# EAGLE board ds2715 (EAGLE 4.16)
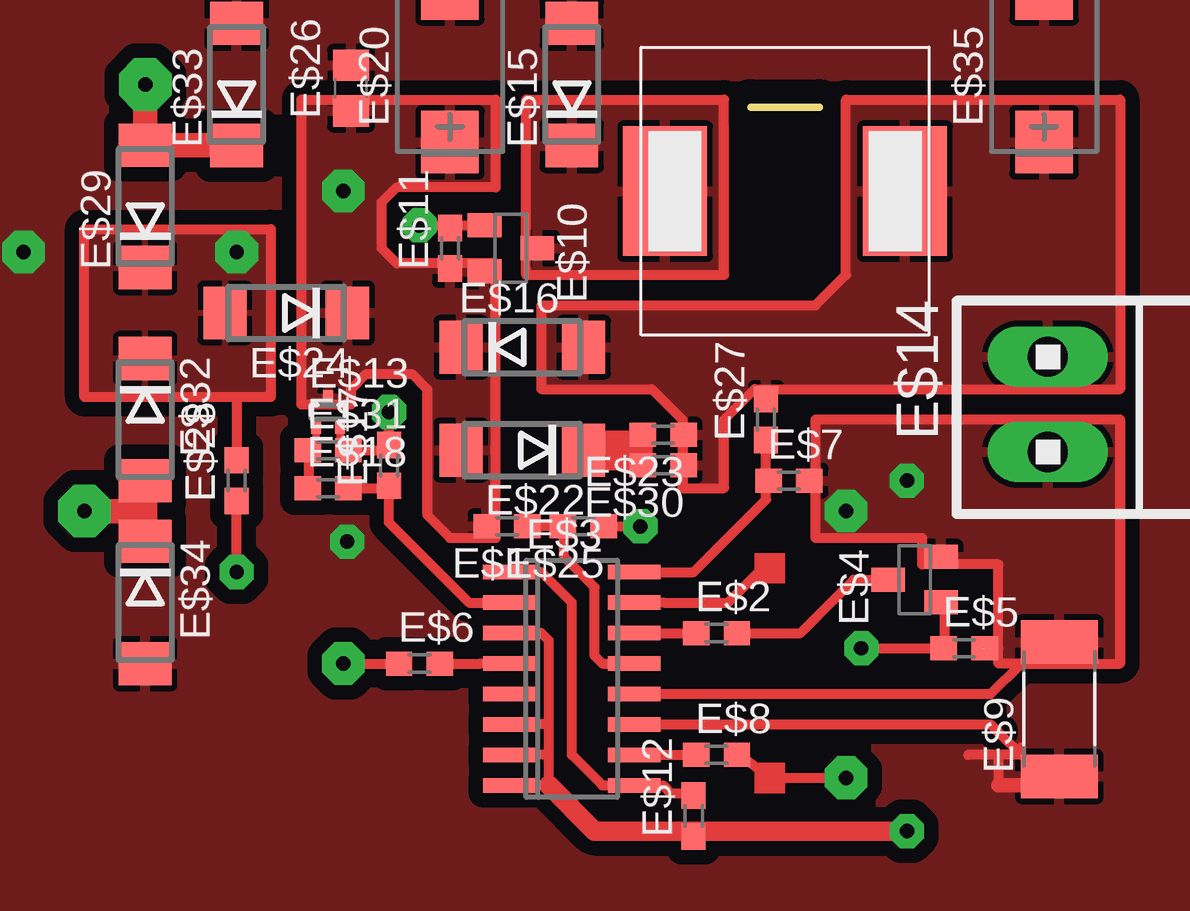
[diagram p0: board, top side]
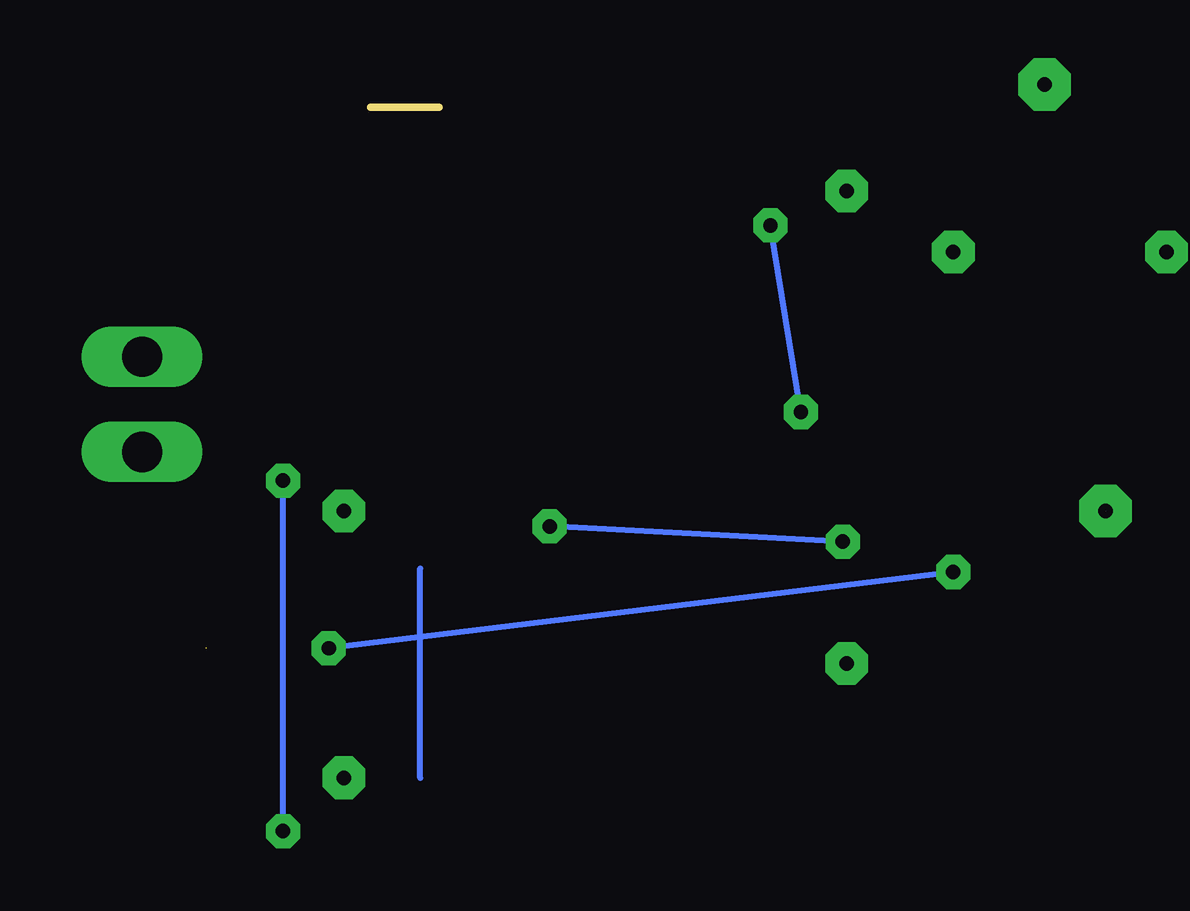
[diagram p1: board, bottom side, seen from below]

Size 2.86 x 0 mm. Coordinates in mm from the lower left corner, seen from the top.
Outline: 0,0 2.86,0
Copper layers (1*16): Top 0.035mm / dielectric 1.5mm / Bottom 0.035mm
Design rules "default": minimum track width 10mil, minimum drill 24mil, track to track 8mil, track to pad 8mil, pad to pad 8mil, via to via 8mil, smd to smd 8mil, copper to edge 40mil, drill to drill 8mil, minimum pad ring 10mil, minimum via ring 8mil, stop-mask expansion 4mil, vias tented up to drill 0mil, thermal gap 10mil

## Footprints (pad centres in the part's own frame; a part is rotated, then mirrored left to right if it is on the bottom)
R0603 = smd 1.1 x 1: 1 -0.85,0; 2 0.85,0
SO16 = smd 0.6 x 2.2: 1 -4.445,-2.6; 2 -3.175,-2.6; 3 -1.905,-2.6; 4 -0.635,-2.6; 5 0.635,-2.6; 6 1.905,-2.6; 7 3.175,-2.6; 8 4.445,-2.6; 9 4.445,2.6; 10 3.175,2.6; 11 1.905,2.6; 12 0.635,2.6; 13 -0.635,2.6; 14 -1.905,2.6; 15 -3.175,2.6; 16 -4.445,2.6
SOT23 = smd 1 x 1.4: 1 -0.95,-1.1; 2 0.95,-1.1; 3 0,1.1
R2512 = smd 1.8 x 3.2: 1 -2.8,0; 2 2.8,0
SC75_INFINEON = smd 0.4 x 0.65: 1 -0.5,-0.575; 2 0,0.575; 3 0.5,-0.575
1X2MTA = drill 1.676 long: 1 1.981,0; 2 -1.981,0
DO214AA = smd 1.8 x 2.2: A 2.55,0; C -2.55,0
CDRH127 = smd 5.4 x 3.5: P$1 0,5; P$2 0,-5
CT7343 = smd 2.6 x 2.4: + -3.2,0; - 3.2,0
C0805 = smd 1.3 x 1.5: 1 -0.95,0; 2 0.95,0

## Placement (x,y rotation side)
E$1  [R0603]  not placed on the board
E$2  [R0603]  not placed on the board
E$3  [SO16]  not placed on the board
E$4  [SOT23]  not placed on the board
E$5  [R0603]  not placed on the board
E$6  [R0603]  not placed on the board
E$7  [R0603]  not placed on the board
E$8  [R0603]  not placed on the board
E$9  [R2512]  not placed on the board
E$10  [SOT23]  not placed on the board
E$11  [R0603]  not placed on the board
E$12  [R0603]  not placed on the board
E$13  [SC75_INFINEON]  not placed on the board
E$14  [1X2MTA]  not placed on the board
E$15  [DO214AA]  not placed on the board
E$16  [DO214AA]  not placed on the board
E$17  [R0603]  not placed on the board
E$18  [R0603]  not placed on the board
E$19  [CDRH127]  not placed on the board
E$20  [CT7343]  not placed on the board
E$22  [DO214AA]  not placed on the board
E$23  [R0603]  not placed on the board
E$24  [DO214AA]  not placed on the board
E$25  [R0603]  not placed on the board
E$26  [C0805]  not placed on the board
E$27  [R0603]  not placed on the board
E$28  [R0603]  not placed on the board
E$29  [DO214AA]  not placed on the board
E$30  [R0603]  not placed on the board
E$31  [R0603]  not placed on the board
E$32  [DO214AA]  not placed on the board
E$33  [DO214AA]  not placed on the board
E$34  [DO214AA]  not placed on the board
E$35  [CT7343]  not placed on the board

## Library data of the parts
E$1-E$8 E$10-E$13 E$15-E$18 E$22-E$34 = ref-packages
E$9 = rcl
E$14 = con-amp
E$19 = sumida
E$20 E$35 = smd-ipc

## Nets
BAT+: E$14.2 E$16.A E$19.P$2 E$23.1 E$27.2 E$30.1 E$35.+
BAT-: E$4.2 E$5.2 E$7.2 E$9.2 E$14.1
DC+: E$24.A E$29.C E$32.C
GND: E$9.1 E$15.A E$20.- E$26.2 E$33.A E$34.A E$35.-
L: E$10.3 E$15.C E$19.P$1
VIN: E$1.2 E$10.2 E$11.1 E$13.2 E$16.C E$20.+ E$22.A E$24.C E$26.1

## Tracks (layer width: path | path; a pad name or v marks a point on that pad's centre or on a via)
BAT+
  Top 0.406: -1.11,-13.02 0.16,-11.75 15.4,-11.75 15.4,0.32 3.97,0.32 3.97,-6.99 2.7,-8.26 2.7,-8.25 -8.73,-8.25 -8.73,-11.75 -4.13,-11.75 -2.86,-13.02 -2.86,-15.88 -1.11,-15.88 -1.11,-13.02
  pour Top (isolate 0.61): -8.73,-11.75 -8.73,-8.25 2.7,-8.25 3.97,-6.98 3.97,0.32 15.4,0.32 15.4,-11.75 0.16,-11.75 -1.11,-13.02 -1.11,-15.87 -2.86,-15.87 -2.86,-13.02 -4.13,-11.75
BAT-  (via drill 0.6 pad 1.42, 0.6 pad 1.78)  (1 unrouted)
  Top 0.406: 11.27,-23.18 10.32,-23.18 10.32,-22.54 | 11.27,-23.18 15.4,-23.18 15.4,-13.02 2.7,-13.02 2.7,-17.94 7.14,-17.94 7.14,-19.05 10.32,-19.05 10.32,-22.54 | -4.92,-24.45 10,-24.45 11.27,-23.18 | 10.32,-22.54 9.68,-22.54
  other vias: 6.51,-15.56 3.97,-16.83
  pour Top (isolate 0.61): 2.7,-13.02 15.4,-13.02 15.4,-23.18 10.32,-23.18 10.32,-19.05 7.14,-19.05 7.14,-17.94 2.7,-17.94
DC+  (via drill 0.6 pad 1.78)
  Top 0.406: -21.43,-12.06 -20,-12.06 -20,-5.08 -27.78,-5.08 -27.78,-12.06 -21.43,-12.06 | -21.43,-12.06 -21.43,-14.29
  other vias: -21.43,-6.03
  pour Top (isolate 0.61): -27.78,-12.06 -27.78,-5.08 -20,-5.08 -20,-12.06
GND  (via drill 0.6 pad 1.42, 0.6 pad 1.78)
  Top 0.406: 10.32,-26.99 10.32,-28.26 | 11.27,-26.99 10.32,-26.99 | 11.27,-26.99 11.27,-26.67 | 10.32,-26.99 9.05,-26.99 | 10.32,-26.03 11.27,-26.99
  Top 0.61: 10.32,-28.26 11.59,-28.26
  Bottom 0.254: v-16.83,-18.1 v-4.6,-17.46
  other vias: -30.32,-6.03
  pour Top (isolate 0.61): -36.67,-33.34 -36.67,7.3 21.75,7.3 21.75,-33.34
L
  Top 0.406: -9.37,-6.98 -9.37,0.32 -1.11,0.32 -1.11,-6.98 -9.37,-6.98
  pour Top (isolate 0.61): -9.37,-6.98 -9.37,0.32 -1.11,0.32 -1.11,-6.98
S$1
  Top 0.406: -10,-21.91 -8.73,-21.91 -8.41,-22.22 -8.41,-25.72 | -8.41,-25.72 -10,-25.72 | -8.41,-26.99 -8.41,-25.72 | -8.41,-26.99 -10,-26.99 | -8.41,-26.99 -8.41,-28.26 -9.68,-28.26
  Top 0.813: 6.51,-30.16 -6.51,-30.16 -8.41,-28.26
S$2
  Top 0.406: -2.38,-28.57 -3.33,-28.57 -3.65,-28.26 -6.19,-28.26 -7.46,-26.99 -7.46,-20.64 -8.73,-19.37 -10,-19.37
S$3
  Top 0.406: -16.83,-14.29 -15.56,-14.29
S$4
  Top 0.406: -10,-20.64 -11.75,-20.64 -15.08,-17.3 -15.08,-15.56
S$5
  Bottom 0.254: -15.08,-12.7 -13.81,-4.92
S$6  (via drill 0.6 pad 1.78)
  other vias: 3.97,-27.94
S$7
  Top 0.406: -12.54,-23.18 -11.27,-23.18
S$8  (via drill 0.6 pad 1.78)
  Top 0.406: v-16.99,-23.18 -15.08,-23.18
S$9
  Top 0.406: -4.92,-19.37 -2.38,-19.37 0.63,-16.35 0.63,-13.97
S$10
  Top 0.406: -0.48,-26.99 0.79,-27.94 3.97,-27.94
S$11
  Top 0.406: -4.92,-21.91 -2.38,-21.91
S$12
  Top 0.406: -4.92,-25.72 10,-25.72 10.32,-26.03
S$13
  Bottom 0.254: -21.43,-19.37 4.6,-22.54
S$14
  Top 0.406: -4.92,-26.99 -2.38,-26.99
S$15
  Top 0.406: -13.81,-4.92 -11.27,-4.92
S$16
  Top 0.406: -4.92,-23.18 -6.19,-23.18 -6.51,-22.86 -6.51,-20 -7.78,-18.73 -7.78,-17.46 -8.73,-17.46
S$17
  Top 0.406: -3.65,-20.64 -0.95,-20.64 0.32,-19.37
S$18
  Top 0.305: -18.42,-14.6 -18.12,-14.29 -18.12,-13.49
  Top 0.406: -18.42,-15.88 -18.42,-14.6
S$19
  Top 0.305: -17.13,-14.29 -17.13,-13.33
S$20
  Top 0.406: -16.67,-15.88 -15.08,-15.88
S$21
  Top 0.406: -21.43,-19.37 -21.43,-16.83
S$22  (via drill 0.6 pad 1.42)
  other vias: -13.81,-4.92
S$23  (via drill 0.6 pad 1.42)
  other vias: -15.08,-12.7
S$24
  Top 0.406: -15.08,-13.97 -15.08,-12.7
S$25
  Top 0.406: -5.87,-17.46 -4.6,-17.46
S$26
  Top 1.676: -6.19,-14.29 -4.92,-14.29
S$27
  Top 0.406: -0.48,-21.91 2.06,-21.91 4.29,-19.69 5.4,-19.69
S$28
  Top 1.016: -25.24,0.95 -25.24,-1.59 -21.59,-1.59
S$29
  Top 0.406: 8.1,-22.54 8.1,-20.64
S$30
  Top 0.406: 4.6,-22.54 8.1,-22.54
S$31
  Bottom 0.254: 0.79,-27.94 0.79,-19.21
S$32  (via drill 0.6 pad 1.42)
  other vias: -21.43,-19.37
S$33  (via drill 0.6 pad 1.42)
  other vias: 6.51,-30.16
S$34  (via drill 0.6 pad 1.42)
  other vias: 4.6,-22.54
S$35
  Bottom 0.254: 6.51,-30.16 6.51,-15.56
S$36  (via drill 0.6 pad 2.18)  (1 unrouted)
  Top 1.016: -25.24,-16.83 -25.24,-15.88 | -25.24,-16.83 -25.24,-18.1 | v-27.78,-16.83 -25.24,-16.83
S$38  (via drill 0.6 pad 2.18)
  other vias: -25.24,0.95
VIN  (via drill 0.6 pad 1.78)
  Top 0.406: -10.64,-17.94 -10.64,-17.15 | -10.64,-17.94 -10.64,-6.51 -14.76,-6.51 | -10.64,-17.94 -12.54,-17.94 -13.49,-16.99 -13.49,-11.75 -14.13,-11.11 -16.03,-11.11 -16.67,-11.75 -16.67,-12.38 -18.73,-12.38 -18.73,0.32 -10.64,0.32 -10.64,-3.33 -14.76,-3.33 | -14.76,-3.33 | -14.76,-3.33 -15.4,-3.97 -15.4,-5.87 -14.76,-6.51 | -14.76,-6.51
  other vias: -16.99,-3.49
  pour Top (isolate 0.61): -18.73,0.32 -10.64,0.32 -10.64,-3.33 -14.76,-3.33 -14.76,-3.33 -15.4,-3.97 -15.4,-5.87 -14.76,-6.51 -14.76,-6.51 -10.64,-6.51 -10.64,-17.94 -12.54,-17.94 -13.49,-16.99 -13.49,-11.75 -14.13,-11.11 -16.03,-11.11 -16.67,-11.75 -16.67,-12.38 -18.73,-12.38
(copper drawn outside any net)
  shapes: Top area x2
